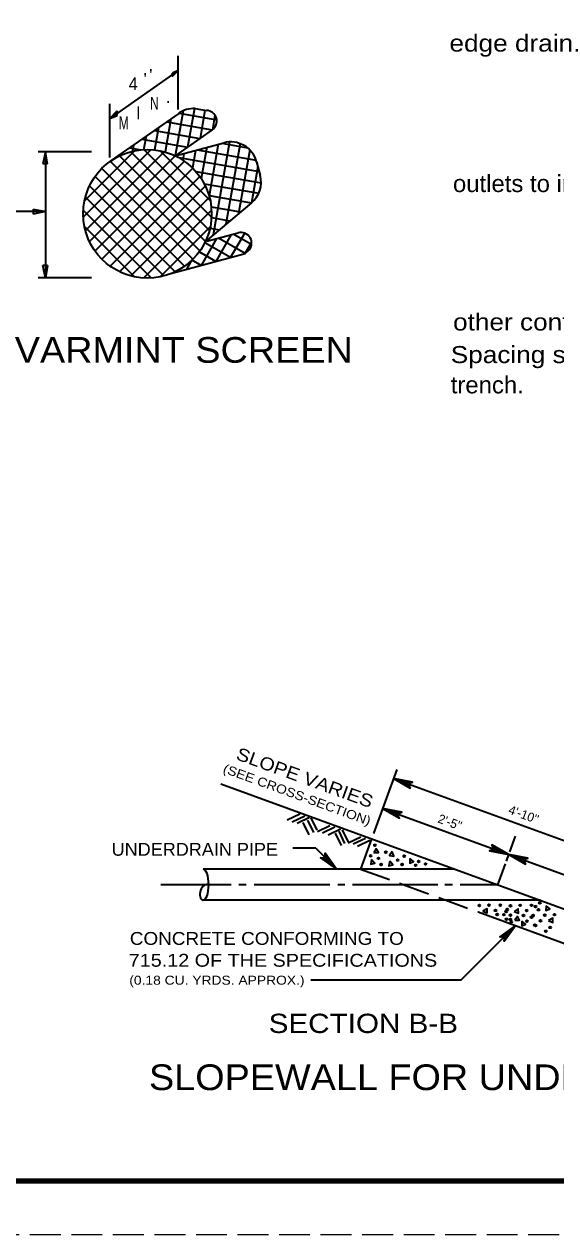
# Model space of a CAD drawing. Extents: x -48732 to -48696.6, y -117659.8 to -117637.8.
# Drawn here: x -48710.3 to -48705.33, y -117659.85 to -117648.54 of the extents above; entities that cross this region are included whole.
import ezdxf

# ---------------------------------------------------------------- set-up
doc = ezdxf.new("R2010")
doc.units = 0
doc.header["$LTSCALE"] = 0.048
doc.linetypes.add('LONG_DASHED', pattern=[7.5, 6, -1.5])
doc.layers.add('1', color=7, linetype='Continuous', lineweight=25)
doc.layers.add('3', color=7, linetype='Continuous', lineweight=35)

msp = doc.modelspace()

# ---------------------------------------------------------------- linework, layer by layer
at = {"layer": '1', "linetype": 'LONG_DASHED'}
msp.add_line((-48696.76492, -117659.84817), (-48731.96492, -117659.84817), dxfattribs=at)
at = {"layer": '1', "lineweight": 158}
msp.add_lwpolyline([(-48696.84825, -117638.34817), (-48696.84825, -117659.34817), (-48729.34825, -117659.34817)], dxfattribs=at)
at = {"layer": '3'}
for p, q in [((-48708.85958, -117649.34058), (-48708.85958, -117648.84058)), ((-48708.85958, -117648.97558), (-48709.49958, -117649.42358)), ((-48708.85958, -117648.97558), (-48708.91158, -117649.00158)), ((-48709.49958, -117649.78858), (-48709.49958, -117649.28858)), ((-48709.49958, -117649.42358), (-48709.42858, -117649.35258)), ((-48709.42858, -117649.39758), (-48709.42858, -117649.35258)), ((-48708.70758, -117649.33058), (-48708.77258, -117649.69158)), ((-48708.70158, -117649.33158), (-48708.59558, -117649.34858)), ((-48708.60958, -117649.34658), (-48708.65558, -117649.61058)), ((-48709.49958, -117649.42358), (-48709.42858, -117649.39758)), ((-48708.85458, -117649.37658), (-48709.49458, -117649.82458)), ((-48708.92758, -117649.42758), (-48708.98258, -117649.73658)), ((-48708.96758, -117649.45558), (-48708.54158, -117649.53058)), ((-48708.81258, -117649.35358), (-48708.88758, -117649.77258)), ((-48708.85158, -117649.37458), (-48708.49958, -117649.43658)), ((-48708.51658, -117649.39258), (-48708.54058, -117649.53058)), ((-48709.08258, -117649.53658), (-48708.65658, -117649.61158)), ((-48709.04458, -117649.50958), (-48709.08058, -117649.71758)), ((-48708.54158, -117649.53058), (-48708.88758, -117649.77258)), ((-48709.27658, -117649.67158), (-48709.28658, -117649.73058)), ((-48709.19858, -117649.61758), (-48708.77358, -117649.69258)), ((-48709.15958, -117649.58958), (-48709.18258, -117649.72058)), ((-48708.88758, -117649.77258), (-48708.43358, -117649.65158)), ((-48708.48558, -117649.66558), (-48708.57058, -117650.14758)), ((-48708.38158, -117649.64358), (-48708.53258, -117650.51258)), ((-48708.45158, -117649.65658), (-48708.21358, -117649.69758)), ((-48708.28158, -117649.65958), (-48708.41358, -117650.41258)), ((-48709.66858, -117649.73458), (-48710.16858, -117649.73458)), ((-48710.10058, -117649.73458), (-48710.12558, -117649.84958)), ((-48710.10058, -117649.73458), (-48710.10058, -117650.91358)), ((-48710.07958, -117649.84958), (-48710.10058, -117649.73458)), ((-48709.74658, -117650.34758), (-48709.11358, -117649.71458)), ((-48709.73558, -117650.19458), (-48709.26658, -117649.72558)), ((-48709.72658, -117650.46958), (-48708.99158, -117649.73458)), ((-48709.68858, -117650.57358), (-48708.88758, -117649.77258)), ((-48708.60558, -117650.57358), (-48709.40658, -117649.77258)), ((-48709.31358, -117649.69858), (-48709.20758, -117649.71758)), ((-48708.56758, -117650.46958), (-48709.30258, -117649.73458)), ((-48708.54758, -117650.34758), (-48709.18058, -117649.71458)), ((-48708.55858, -117650.19458), (-48709.02758, -117649.72558)), ((-48708.85458, -117649.78958), (-48708.10358, -117649.92058)), ((-48708.80558, -117649.75058), (-48708.81658, -117649.81258)), ((-48708.69858, -117649.72258), (-48708.72658, -117649.88558)), ((-48708.68358, -117649.71858), (-48708.13258, -117649.81458)), ((-48708.59258, -117649.69358), (-48708.64358, -117649.98658)), ((-48708.19058, -117649.71858), (-48708.29558, -117650.31258)), ((-48710.07958, -117649.84958), (-48710.12558, -117649.84958)), ((-48709.63658, -117650.66158), (-48708.79958, -117649.82458)), ((-48708.72258, -117650.73858), (-48709.57258, -117649.89058)), ((-48709.57158, -117650.73858), (-48708.72258, -117649.88958)), ((-48708.65758, -117650.66158), (-48709.49458, -117649.82458)), ((-48708.11658, -117649.87158), (-48708.17558, -117650.21258)), ((-48708.12758, -117649.82958), (-48708.09358, -117649.95758)), ((-48708.79958, -117650.80358), (-48709.63658, -117649.96658)), ((-48709.49458, -117650.80358), (-48708.65758, -117649.96658)), ((-48708.69458, -117649.91958), (-48708.08558, -117650.02558)), ((-48708.88758, -117650.85558), (-48709.68858, -117650.05458)), ((-48709.40658, -117650.85558), (-48708.60558, -117650.05458)), ((-48708.61658, -117650.03358), (-48708.10758, -117650.12258)), ((-48708.57158, -117650.14358), (-48708.17558, -117650.21258)), ((-48708.99258, -117650.89358), (-48709.72658, -117650.15858)), ((-48709.30258, -117650.89358), (-48708.56758, -117650.15858)), ((-48708.17558, -117650.21258), (-48708.60558, -117650.57358)), ((-48708.55058, -117650.24958), (-48708.27658, -117650.29758)), ((-48710.10058, -117650.29358), (-48710.42558, -117650.29358)), ((-48710.21558, -117650.27258), (-48710.21558, -117650.31858)), ((-48710.21558, -117650.27258), (-48710.10058, -117650.29358)), ((-48710.10058, -117650.29358), (-48710.21558, -117650.31858)), ((-48709.11358, -117650.91358), (-48709.74658, -117650.28058)), ((-48709.18058, -117650.91358), (-48708.55458, -117650.28758)), ((-48708.54758, -117650.35058), (-48708.37658, -117650.38058)), ((-48709.26658, -117650.90258), (-48709.73558, -117650.43358)), ((-48709.02758, -117650.90258), (-48708.55458, -117650.42958)), ((-48708.56258, -117650.44958), (-48708.47658, -117650.46458)), ((-48708.64258, -117650.79658), (-48708.49758, -117650.54458)), ((-48708.36958, -117650.72358), (-48708.61158, -117650.58458)), ((-48708.60558, -117650.57358), (-48708.29958, -117650.49158)), ((-48708.50558, -117650.75958), (-48708.36058, -117650.50758)), ((-48708.23258, -117650.68658), (-48708.48458, -117650.54158)), ((-48708.36958, -117650.72358), (-48708.23758, -117650.49458)), ((-48708.18258, -117650.59958), (-48708.34758, -117650.50458)), ((-48708.23258, -117650.68658), (-48708.17358, -117650.58358)), ((-48708.92758, -117650.87258), (-48708.23258, -117650.68658)), ((-48708.50658, -117650.75958), (-48708.66358, -117650.66958)), ((-48708.20558, -117650.66158), (-48708.23258, -117650.68658)), ((-48710.10058, -117650.91358), (-48710.12558, -117650.79858)), ((-48710.07958, -117650.79858), (-48710.12558, -117650.79858)), ((-48710.07958, -117650.79858), (-48710.10058, -117650.91358)), ((-48708.77958, -117650.83258), (-48708.72858, -117650.74458)), ((-48708.64458, -117650.79658), (-48708.73058, -117650.74658)), ((-48709.66858, -117650.91358), (-48710.16858, -117650.91358)), ((-48706.8185, -117655.505), (-48707.0345, -117656.101)), ((-48706.8485, -117655.587), (-48704.4975, -117656.442)), ((-48707.8405, -117655.973), (-48707.7245, -117655.918)), ((-48707.7935, -117655.991), (-48707.6775, -117655.936)), ((-48707.7485, -117656.005), (-48707.6325, -117655.95)), ((-48707.6365, -117656.113), (-48707.6915, -117655.997)), ((-48707.5935, -117656.093), (-48707.6485, -117655.977)), ((-48707.5625, -117656.07), (-48707.6175, -117655.954)), ((-48707.5585, -117656.081), (-48707.4425, -117656.026)), ((-48707.5115, -117656.095), (-48707.3955, -117656.04)), ((-48707.4585, -117656.114), (-48707.3425, -117656.059)), ((-48707.3345, -117656.213), (-48707.3895, -117656.097)), ((-48707.3025, -117656.196), (-48707.3575, -117656.08)), ((-48707.2695, -117656.182), (-48707.3245, -117656.066)), ((-48707.2705, -117656.187), (-48707.1545, -117656.132)), ((-48705.7115, -117656.126), (-48705.7645, -117656.271)), ((-48707.5755, -117656.239), (-48707.7895, -117656.239)), ((-48707.5755, -117656.239), (-48707.3815, -117656.433)), ((-48707.2255, -117656.199), (-48707.1095, -117656.144)), ((-48707.1855, -117656.218), (-48707.0695, -117656.163)), ((-48707.0535, -117656.152), (-48707.1555, -117656.433)), ((-48705.7695, -117656.288), (-48705.7955, -117656.359)), ((-48706.2775, -117656.433), (-48708.6265, -117656.433)), ((-48705.8065, -117656.385), (-48705.8765, -117656.579)), ((-48708.3635, -117656.579), (-48709.0225, -117656.579)), ((-48708.2255, -117656.579), (-48708.2925, -117656.579)), ((-48707.4445, -117656.579), (-48708.1495, -117656.579)), ((-48707.3015, -117656.579), (-48707.3685, -117656.579)), ((-48706.4355, -117656.579), (-48707.2305, -117656.579)), ((-48706.2975, -117656.579), (-48706.3685, -117656.579)), ((-48705.8765, -117656.579), (-48706.2265, -117656.579)), ((-48705.4755, -117656.725), (-48708.6265, -117656.725)), ((-48706.0585, -117656.833), (-48705.0875, -117657.186)), ((-48706.2195, -117657.472), (-48705.7075, -117656.96)), ((-48706.2195, -117657.472), (-48707.6215, -117657.472))]:
    msp.add_line(p, q, dxfattribs=at)
at = {"layer": '3', "linetype": 'LONG_DASHED'}
msp.add_line((-48707.1555, -117656.433), (-48706.0575, -117656.833), dxfattribs=at)
at = {"layer": '3'}
for points in [[(-48708.85958, -117648.97558), (-48708.91158, -117649.02858), (-48708.91158, -117649.00158)], [(-48708.4625, -117655.638), (-48704.7035, -117657.006), (-48704.9085, -117657.57)], [(-48706.6695, -117655.621), (-48706.8485, -117655.587), (-48706.6915, -117655.677), (-48706.6925, -117655.672), (-48706.8315, -117655.594), (-48706.6745, -117655.623), (-48706.6805, -117655.625), (-48706.8145, -117655.6), (-48706.6965, -117655.667), (-48706.6995, -117655.662), (-48706.7975, -117655.607), (-48706.6855, -117655.626), (-48706.6915, -117655.629), (-48706.7805, -117655.613), (-48706.7025, -117655.658), (-48706.7055, -117655.652), (-48706.7645, -117655.619), (-48706.6985, -117655.63), (-48706.7035, -117655.634), (-48706.7485, -117655.624), (-48706.7085, -117655.647), (-48706.7105, -117655.641), (-48706.7305, -117655.632), (-48706.7095, -117655.634), (-48706.6695, -117655.621), (-48706.7145, -117655.638), (-48706.6915, -117655.677)], [(-48706.7715, -117655.903), (-48706.9505, -117655.869), (-48706.7935, -117655.959), (-48706.7945, -117655.954), (-48706.9335, -117655.876), (-48706.7765, -117655.905), (-48706.7825, -117655.907), (-48706.9165, -117655.882), (-48706.7985, -117655.949), (-48706.8015, -117655.944), (-48706.8995, -117655.889), (-48706.7875, -117655.908), (-48706.7935, -117655.911), (-48706.8825, -117655.895), (-48706.8045, -117655.94), (-48706.8075, -117655.934), (-48706.8665, -117655.901), (-48706.8005, -117655.912), (-48706.8055, -117655.916), (-48706.8505, -117655.906), (-48706.8105, -117655.929), (-48706.8125, -117655.923), (-48706.8325, -117655.914), (-48706.8115, -117655.916), (-48706.7715, -117655.903), (-48706.8165, -117655.92), (-48706.7935, -117655.959)], [(-48706.9505, -117655.869), (-48705.7725, -117656.297), (-48704.6005, -117656.724)], [(-48705.9515, -117656.263), (-48705.7725, -117656.297), (-48705.9295, -117656.207), (-48705.9285, -117656.212), (-48705.7895, -117656.29), (-48705.9465, -117656.261), (-48705.9405, -117656.259), (-48705.8065, -117656.284), (-48705.9245, -117656.217), (-48705.9215, -117656.222), (-48705.8235, -117656.277), (-48705.9355, -117656.258), (-48705.9295, -117656.255), (-48705.8405, -117656.271), (-48705.9185, -117656.226), (-48705.9155, -117656.232), (-48705.8565, -117656.265), (-48705.9225, -117656.254), (-48705.9175, -117656.25), (-48705.8725, -117656.26), (-48705.9125, -117656.237), (-48705.9105, -117656.243), (-48705.8905, -117656.252), (-48705.9115, -117656.25), (-48705.9515, -117656.263), (-48705.9065, -117656.246), (-48705.9295, -117656.207)], [(-48707.5295, -117656.327), (-48707.3815, -117656.433), (-48707.4875, -117656.285), (-48707.4875, -117656.29), (-48707.3945, -117656.42), (-48707.5245, -117656.327), (-48707.5185, -117656.328), (-48707.4075, -117656.407), (-48707.4865, -117656.296), (-48707.4855, -117656.302), (-48707.4205, -117656.394), (-48707.5125, -117656.329), (-48707.5065, -117656.329), (-48707.4335, -117656.381), (-48707.4855, -117656.308), (-48707.4845, -117656.314), (-48707.4455, -117656.369), (-48707.5005, -117656.33), (-48707.4945, -117656.33), (-48707.4585, -117656.356), (-48707.4845, -117656.32), (-48707.4835, -117656.326), (-48707.4715, -117656.343), (-48707.4885, -117656.331), (-48707.5295, -117656.327), (-48707.4835, -117656.331), (-48707.4875, -117656.285)], [(-48705.5935, -117656.331), (-48705.7725, -117656.297), (-48705.6155, -117656.387), (-48705.6165, -117656.382), (-48705.7555, -117656.304), (-48705.5985, -117656.333), (-48705.6045, -117656.335), (-48705.7385, -117656.31), (-48705.6205, -117656.377), (-48705.6235, -117656.372), (-48705.7215, -117656.317), (-48705.6095, -117656.336), (-48705.6155, -117656.339), (-48705.7045, -117656.323), (-48705.6265, -117656.368), (-48705.6295, -117656.362), (-48705.6885, -117656.329), (-48705.6225, -117656.34), (-48705.6275, -117656.344), (-48705.6725, -117656.334), (-48705.6325, -117656.357), (-48705.6345, -117656.351), (-48705.6545, -117656.342), (-48705.6335, -117656.344), (-48705.5935, -117656.331), (-48705.6385, -117656.348), (-48705.6155, -117656.387)], [(-48705.8135, -117657.108), (-48705.7075, -117656.96), (-48705.8555, -117657.066), (-48705.8505, -117657.066), (-48705.7205, -117656.973), (-48705.8135, -117657.103), (-48705.8125, -117657.097), (-48705.7335, -117656.986), (-48705.8445, -117657.065), (-48705.8385, -117657.064), (-48705.7465, -117656.999), (-48705.8115, -117657.091), (-48705.8115, -117657.085), (-48705.7595, -117657.012), (-48705.8325, -117657.064), (-48705.8265, -117657.063), (-48705.7715, -117657.024), (-48705.8105, -117657.079), (-48705.8105, -117657.073), (-48705.7845, -117657.037), (-48705.8205, -117657.063), (-48705.8145, -117657.062), (-48705.7975, -117657.05), (-48705.8095, -117657.067), (-48705.8135, -117657.108), (-48705.8095, -117657.062), (-48705.8555, -117657.066)]]:
    msp.add_lwpolyline(points, dxfattribs=at)
for points in [[(-48707.0335, -117656.283), (-48706.9895, -117656.277), (-48707.0115, -117656.245)], [(-48707.0525, -117656.344), (-48707.0615, -117656.388), (-48707.0235, -117656.379)], [(-48706.8835, -117656.359), (-48706.8925, -117656.403), (-48706.8545, -117656.394)], [(-48706.8605, -117656.269), (-48706.8845, -117656.307), (-48706.8455, -117656.312)], [(-48706.6955, -117656.334), (-48706.6965, -117656.378), (-48706.6615, -117656.363)], [(-48706.0125, -117656.826), (-48705.9725, -117656.842), (-48705.9735, -117656.803)], [(-48705.7215, -117656.828), (-48705.6815, -117656.844), (-48705.6825, -117656.805)], [(-48705.4235, -117656.776), (-48705.4245, -117656.82), (-48705.3895, -117656.805)], [(-48705.7165, -117656.909), (-48705.6725, -117656.911), (-48705.6885, -117656.876)], [(-48705.6485, -117656.919), (-48705.6495, -117656.963), (-48705.6145, -117656.948)], [(-48705.4005, -117656.915), (-48705.3605, -117656.931), (-48705.3615, -117656.892)]]:
    msp.add_lwpolyline(points, close=True, dxfattribs=at)
for centre, radius in [((-48709.14758, -117650.31458), 0.60033), ((-48707.0215, -117656.211), 0.00848), ((-48707.0615, -117656.309), 0.00848), ((-48706.9885, -117656.333), 0.00848), ((-48706.9195, -117656.276), 0.00848), ((-48706.8095, -117656.349), 0.00848), ((-48706.7475, -117656.313), 0.00848), ((-48706.6135, -117656.362), 0.00848), ((-48706.9645, -117656.39), 0.00848), ((-48706.7685, -117656.39), 0.00848), ((-48706.6415, -117656.398), 0.00848), ((-48706.5485, -117656.386), 0.00848), ((-48706.0465, -117656.774), 0.00848), ((-48705.9565, -117656.77), 0.00848), ((-48705.8955, -117656.819), 0.00848), ((-48705.8505, -117656.77), 0.00848), ((-48705.7855, -117656.811), 0.00848), ((-48705.7555, -117656.776), 0.00848), ((-48705.6655, -117656.772), 0.00848), ((-48705.6045, -117656.821), 0.00848), ((-48705.5595, -117656.772), 0.00848), ((-48705.5225, -117656.784), 0.00848), ((-48705.4945, -117656.813), 0.00848), ((-48705.4815, -117656.748), 0.00848), ((-48705.8795, -117656.857), 0.00848), ((-48705.8165, -117656.859), 0.00848), ((-48705.7965, -117656.829), 0.00848), ((-48705.7935, -117656.902), 0.00848), ((-48705.7565, -117656.863), 0.00848), ((-48705.7565, -117656.904), 0.00848), ((-48705.7475, -117656.927), 0.00848), ((-48705.6345, -117656.867), 0.00848), ((-48705.6015, -117656.92), 0.00848), ((-48705.5595, -117656.882), 0.00848), ((-48705.5445, -117656.867), 0.00848), ((-48705.4755, -117656.916), 0.00848), ((-48705.4345, -117656.863), 0.00848), ((-48705.3445, -117656.859), 0.00848), ((-48705.5275, -117656.956), 0.00848), ((-48705.5205, -117656.961), 0.00848), ((-48705.4265, -117657.014), 0.00848), ((-48705.3855, -117656.978), 0.00848)]:
    msp.add_circle(centre, radius, dxfattribs=at)
for centre, radius, start, end in [((-48708.7109, -117649.58139), 0.25, 87.96739, 124.94645), ((-48708.59899, -117649.44891), 0.1, 304.94645, 87.96739), ((-48708.36941, -117649.89353), 0.25, 14.78131, 104.88529), ((-48708.33578, -117650.02098), 0.25, 309.98885, 14.78131), ((-48708.27367, -117650.58828), 0.1, 312.87891, 104.98272)]:
    msp.add_arc(centre, radius, start, end, dxfattribs=at)
for centre, major_axis, ratio, start_param, end_param in [((-48708.6265, -117656.579), (0, -0.146), 0.356198, 6.28318531, 9.42477796), ((-48708.6005, -117656.6515), (0.026, 0.0735), 0.691909, 0, 3.14159265)]:
    msp.add_ellipse(centre, major_axis=major_axis, ratio=ratio, start_param=start_param, end_param=end_param, dxfattribs=at)

# ---------------------------------------------------------------- texts
at = {"layer": '1'}
for s, width, p in [(' edge drain.', 1.15, (-48706.39358, -117648.80025)), ('outlets to insure that all areas shall be free draining.', 1.05, (-48706.29308, -117650.11158)), ('other configurations may be utilized if depth and width are obtained.', 1.15, (-48706.29192, -117651.40417)), ("Spacing shall be 100' maximum in areas designated as requiring lateral", 1.15, (-48706.31367, -117651.70867)), ('trench.', 1.05, (-48706.31367, -117651.99142))]:
    msp.add_text(s, height=0.159, dxfattribs=dict(at, width=width)).set_placement(p)
at = {"layer": '3'}
for s, p in [("'", (-48709.18358, -117649.11858)), ("'", (-48709.13058, -117649.08158)), ('.', (-48708.97558, -117649.28158))]:
    msp.add_text(s, height=0.12, dxfattribs=at).set_placement(p)
for s, height, width, p in [('4', 0.12, 0.95, (-48709.32158, -117649.15958)), ('N', 0.12, 0.7, (-48709.12258, -117649.34258)), ('I', 0.12, 0.9, (-48709.25258, -117649.43258)), ('M', 0.12, 0.7, (-48709.41458, -117649.52558)), ('VARMINT SCREEN', 0.24, 1.1, (-48710.3865, -117651.70567)), ('UNDERDRAIN PIPE', 0.12, 1.05, (-48709.4815, -117656.309)), ('CONCRETE CONFORMING TO', 0.12, 1.1, (-48709.3115, -117657.141)), ('715.12 OF THE SPECIFICATIONS', 0.12, 1.15, (-48709.3215, -117657.345)), ('(0.18 CU. YRDS. APPROX.)', 0.084, 1.15, (-48709.3165, -117657.513)), ('SECTION B-B', 0.18, 1.15, (-48708.0145, -117657.964)), ('SLOPEWALL FOR UNDERDRAIN', 0.24, 1.1, (-48709.1325, -117658.497))]:
    msp.add_text(s, height=height, dxfattribs=dict(at, width=width)).set_placement(p)
at = {"layer": '3', "width": 1.15}
for s, height, rotation, p in [('SLOPE VARIES', 0.12, 340.002, (-48708.3285, -117655.406)), ('(SEE CROSS-SECTION)', 0.084, 339.993, (-48708.4485, -117655.529))]:
    msp.add_text(s, height=height, rotation=rotation, dxfattribs=at).set_placement(p)
at = {"layer": '3'}
for s, rotation, p in [("4'-10''", 339.949, (-48705.7825, -117655.913)), ("2'-5''", 340.033, (-48706.4415, -117655.996))]:
    msp.add_text(s, height=0.084, rotation=rotation, dxfattribs=at).set_placement(p)

doc.saveas('drawing.dxf')
